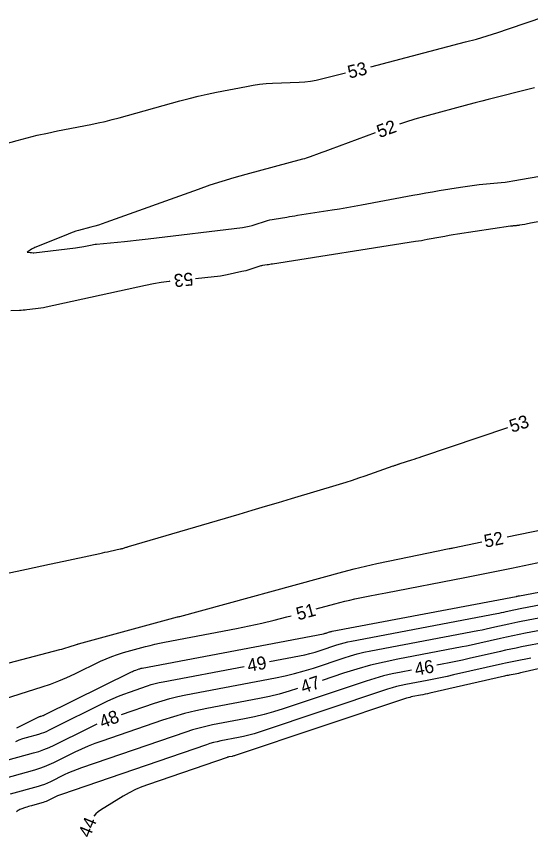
# Model space of a CAD drawing. Extents: x 2384780 to 2405861, y 547869 to 573706.
# Drawn here: x 2390006.1 to 2390085.4, y 552348.1 to 552474.8 of the extents above; entities that cross this region are included whole.
import ezdxf

# ---------------------------------------------------------------- set-up
doc = ezdxf.new("R2010")
doc.units = 0
doc.layers.add('Old_Level_60', color=7, linetype='Continuous')
doc.layers.add('Old_Level_61', color=7, linetype='Continuous')

msp = doc.modelspace()

# ---------------------------------------------------------------- linework, layer by layer
at = {"layer": 'Old_Level_60'}
for points in [[(2390060.75025, 552466.983), (2390075.37925, 552470.815), (2390077.046, 552471.26875), (2390078.70325, 552471.75375), (2390080.351, 552472.27025), (2390081.98925, 552472.81825), (2390087.5915, 552474.752)], [(2389996.453, 552452.94), (2390006.18225, 552455.61525), (2390007.73175, 552456.02575), (2390009.28825, 552456.407), (2390010.8515, 552456.759), (2390012.42175, 552457.082), (2390017.562, 552458.089), (2390018.66125, 552458.31525), (2390019.75525, 552458.56225), (2390020.8445, 552458.83025), (2390021.929, 552459.11875), (2390031.29975, 552461.7095), (2390032.6995, 552462.0825), (2390034.10525, 552462.42925), (2390035.5175, 552462.75), (2390036.93575, 552463.0445), (2390041.579, 552463.9635), (2390042.57625, 552464.14125), (2390043.578, 552464.28025), (2390044.5845, 552464.381), (2390045.5955, 552464.443), (2390049.6985, 552464.6165), (2390050.57475, 552464.6755), (2390051.4445, 552464.7785), (2390052.308, 552464.925), (2390053.16525, 552465.1155), (2390056.8645, 552466.03475)], [(2390086.025, 552463.72925), (2390084.58675, 552463.36875), (2390079.885, 552462.2035), (2390078.87825, 552461.951), (2390077.873, 552461.693), (2390076.869, 552461.429), (2390075.86675, 552461.15975), (2390069.0175, 552459.29775), (2390067.555, 552458.88275), (2390066.1025, 552458.43625), (2390065.1825, 552458.131)], [(2390061.418, 552456.77975), (2390054.48675, 552454.224), (2390054.06225, 552454.0675), (2390053.638, 552453.911), (2390053.2135, 552453.7545), (2390052.78925, 552453.598), (2390051.403, 552453.08675), (2390051.10475, 552452.98075), (2390050.8045, 552452.8815), (2390050.502, 552452.78925), (2390050.19725, 552452.704), (2390041.478, 552450.37075), (2390039.61575, 552449.8515), (2390037.7655, 552449.293), (2390035.92775, 552448.6955), (2390034.102, 552448.05925), (2390019.879, 552442.933), (2390019.30625, 552442.73375), (2390018.7295, 552442.5475), (2390018.14875, 552442.3745), (2390017.564, 552442.21425), (2390015.647, 552441.71225), (2390015.23825, 552441.598), (2390014.834, 552441.471), (2390014.434, 552441.331), (2390014.03825, 552441.178), (2390009.0775, 552439.1685), (2390008.906, 552439.0945), (2390008.738, 552439.01325), (2390008.57375, 552438.925), (2390008.41325, 552438.82925), (2390007.8025, 552438.4475), (2390007.75525, 552438.41125), (2390007.74325, 552438.38425), (2390007.76675, 552438.36625), (2390007.82575, 552438.35725)], [(2390007.82575, 552438.35725), (2390008.18325, 552438.33675), (2390008.24025, 552438.33325), (2390008.29725, 552438.32925), (2390008.354, 552438.32475), (2390008.411, 552438.32), (2390008.65275, 552438.2985), (2390008.6645, 552438.2975), (2390008.6765, 552438.297), (2390008.68825, 552438.297), (2390008.70025, 552438.29725), (2390008.739, 552438.29875), (2390008.74725, 552438.299), (2390008.7555, 552438.2995), (2390008.764, 552438.30025), (2390008.77225, 552438.30125), (2390015.169, 552439.04025), (2390015.49575, 552439.082), (2390015.821, 552439.132), (2390016.145, 552439.19), (2390016.4675, 552439.25625), (2390017.51925, 552439.486), (2390017.74525, 552439.53175), (2390017.97225, 552439.57075), (2390018.20025, 552439.60325), (2390018.42925, 552439.629), (2390022.72825, 552440.04725), (2390023.64925, 552440.13975), (2390024.56975, 552440.2375), (2390025.4895, 552440.3405), (2390026.40875, 552440.449), (2390040.97675, 552442.2115), (2390041.47425, 552442.284), (2390041.9665, 552442.38075), (2390042.4535, 552442.50125), (2390042.935, 552442.646), (2390044.49925, 552443.1575), (2390044.836, 552443.2605), (2390045.17625, 552443.3505), (2390045.5195, 552443.427), (2390045.866, 552443.49025), (2390047.7965, 552443.80425), (2390048.21025, 552443.87125), (2390048.624, 552443.9375), (2390049.038, 552444.00325), (2390049.452, 552444.06825), (2390054.77, 552444.90025), (2390055.90875, 552445.0825), (2390057.04625, 552445.27325), (2390058.18225, 552445.47225), (2390059.317, 552445.6795), (2390067.2235, 552447.1535), (2390068.23875, 552447.34), (2390069.25475, 552447.522), (2390070.27175, 552447.699), (2390071.2895, 552447.871), (2390074.61575, 552448.42525), (2390075.3295, 552448.5375), (2390076.04475, 552448.63725), (2390076.76175, 552448.724), (2390077.48025, 552448.79775), (2390080.29325, 552449.06175), (2390080.89525, 552449.1245), (2390081.49575, 552449.19925), (2390082.09425, 552449.28625), (2390082.69125, 552449.3855), (2390090.682, 552450.796)], [(2390113.026, 552447.73525), (2390085.41125, 552442.83475), (2390085.185, 552442.7945), (2390084.9585, 552442.7545), (2390084.73225, 552442.7145), (2390084.50575, 552442.6745), (2390083.725, 552442.5365), (2390083.587, 552442.51375), (2390083.4485, 552442.4935), (2390083.30975, 552442.47625), (2390083.1705, 552442.46175), (2390082.7155, 552442.419), (2390082.618, 552442.40925), (2390082.52075, 552442.398), (2390082.4235, 552442.3855), (2390082.3265, 552442.3715), (2390074.117, 552441.137), (2390073.47325, 552441.0375), (2390072.83025, 552440.932), (2390072.1885, 552440.821), (2390071.5475, 552440.7045), (2390069.455, 552440.3145), (2390069.00625, 552440.2325), (2390068.557, 552440.15375), (2390068.10725, 552440.0785), (2390067.657, 552440.00625), (2390045.5795, 552436.55275), (2390045.37, 552436.51975), (2390045.16025, 552436.4865), (2390044.95075, 552436.45275), (2390044.74125, 552436.419), (2390044.057, 552436.3075), (2390043.911, 552436.281), (2390043.76625, 552436.24875), (2390043.623, 552436.211), (2390043.48125, 552436.1675), (2390042.0745, 552435.7075), (2390041.772, 552435.61275), (2390041.46725, 552435.526), (2390041.1605, 552435.447), (2390040.85175, 552435.376), (2390038.564, 552434.881), (2390038.07275, 552434.782), (2390037.57925, 552434.6975), (2390037.0835, 552434.6275), (2390036.58525, 552434.57175), (2390033.703, 552434.29125)], [(2390029.72375, 552433.887), (2390029.64225, 552433.87775), (2390028.425, 552433.70475), (2390027.21325, 552433.49575), (2390026.00725, 552433.25125), (2390010.6645, 552429.902), (2390010.258, 552429.81875), (2390009.84975, 552429.7455), (2390009.43975, 552429.6825), (2390009.028, 552429.62975), (2390007.68025, 552429.474), (2390007.39125, 552429.4435), (2390007.10175, 552429.4185), (2390006.812, 552429.39925), (2390006.52175, 552429.3855), (2390005.18, 552429.3355)], [(2390002.024, 552388.313), (2390007.60775, 552389.471), (2390008.804, 552389.7205), (2390009.99975, 552389.9725), (2390011.19475, 552390.2275), (2390012.3895, 552390.485), (2390018.9345, 552391.90375), (2390019.328, 552391.98925), (2390019.72125, 552392.07475), (2390020.1145, 552392.16075), (2390020.50775, 552392.247), (2390022.085, 552392.593), (2390022.2135, 552392.6225), (2390022.3415, 552392.65425), (2390022.469, 552392.68825), (2390022.59575, 552392.72475), (2390023.00875, 552392.84725), (2390023.09725, 552392.8735), (2390023.186, 552392.8995), (2390023.2745, 552392.92575), (2390023.363, 552392.95175), (2390040.45075, 552397.97675), (2390042.46825, 552398.57175), (2390044.48525, 552399.16975), (2390046.501, 552399.771), (2390048.516, 552400.375), (2390055.9445, 552402.60875), (2390056.92925, 552402.91075), (2390057.91025, 552403.22375), (2390058.88775, 552403.5475), (2390059.8615, 552403.88225), (2390064.18125, 552405.394), (2390064.28975, 552405.432), (2390064.3985, 552405.4695), (2390064.50725, 552405.50675), (2390064.61625, 552405.5435), (2390064.97225, 552405.66375), (2390065.0485, 552405.68925), (2390065.125, 552405.71425), (2390065.20175, 552405.73925), (2390065.2785, 552405.7635), (2390067.07725, 552406.3305), (2390067.4625, 552406.453), (2390067.84675, 552406.5775), (2390068.2305, 552406.70425), (2390068.6135, 552406.83325), (2390081.88025, 552411.33725)], [(2390081.803, 552394.48775), (2390098.54775, 552397.934)], [(2389988.47825, 552370.69975), (2390012.75875, 552377.06075), (2390013.07925, 552377.14675), (2390013.39875, 552377.23675), (2390013.71725, 552377.3305), (2390014.03475, 552377.428), (2390015.48125, 552377.88175), (2390015.497, 552377.887), (2390015.51275, 552377.893), (2390015.528, 552377.8995), (2390015.54325, 552377.9065), (2390015.59225, 552377.9305), (2390015.60275, 552377.93525), (2390015.61375, 552377.93975), (2390015.62475, 552377.9435), (2390015.63575, 552377.947), (2390030.90325, 552382.10725), (2390030.939, 552382.1165), (2390030.97475, 552382.12525), (2390031.011, 552382.13325), (2390031.047, 552382.1405), (2390031.16575, 552382.16325), (2390031.191, 552382.16825), (2390031.21625, 552382.17375), (2390031.24125, 552382.18), (2390031.26625, 552382.1865), (2390056.44475, 552389.0425), (2390058.17925, 552389.5005), (2390059.92, 552389.9315), (2390061.6675, 552390.33575), (2390063.42125, 552390.71325), (2390071.16525, 552392.3175), (2390071.39275, 552392.36425), (2390071.6205, 552392.41025), (2390071.8485, 552392.4555), (2390072.0765, 552392.49975), (2390072.82175, 552392.6435), (2390072.9815, 552392.6745), (2390073.141, 552392.706), (2390073.3005, 552392.738), (2390073.46, 552392.7705), (2390077.885, 552393.68125)], [(2390052.30775, 552383.349), (2390055.19325, 552384.13475), (2390055.966, 552384.33875), (2390056.7415, 552384.53075), (2390057.52, 552384.711), (2390058.30125, 552384.879), (2390060.85825, 552385.40875), (2390061.40625, 552385.5215), (2390061.95475, 552385.632), (2390062.50375, 552385.74075), (2390063.053, 552385.84775), (2390075.27075, 552388.20175), (2390077.06925, 552388.55125), (2390078.86675, 552388.9065), (2390080.663, 552389.2675), (2390082.458, 552389.634), (2390088.32025, 552390.8405)], [(2390045.118, 552375.22925), (2390049.741, 552376.1075), (2390050.552, 552376.27575), (2390051.356, 552376.471), (2390052.153, 552376.693), (2390052.943, 552376.94225), (2390055.51225, 552377.8), (2390056.06525, 552377.97425), (2390056.62325, 552378.1295), (2390057.186, 552378.266), (2390057.754, 552378.38325), (2390080.2245, 552382.63475), (2390080.58275, 552382.7045), (2390080.9405, 552382.7775), (2390081.2975, 552382.854), (2390081.65375, 552382.934), (2390082.81625, 552383.2005), (2390083.0655, 552383.2565), (2390083.3155, 552383.31), (2390083.56575, 552383.361), (2390083.81675, 552383.40975), (2390098.63925, 552386.21275)], [(2390022.25675, 552367.03975), (2390027.3615, 552368.788), (2390028.55025, 552369.1715), (2390029.75025, 552369.51225), (2390030.96175, 552369.81), (2390032.1845, 552370.065), (2390046.02475, 552372.69425), (2390047.5135, 552373.00325), (2390048.98975, 552373.3615), (2390050.45275, 552373.76925), (2390051.903, 552374.2265), (2390056.61925, 552375.801), (2390057.6345, 552376.121), (2390058.65875, 552376.40625), (2390059.692, 552376.6565), (2390060.73425, 552376.872), (2390077.24775, 552379.9965), (2390077.915, 552380.126), (2390078.581, 552380.262), (2390079.2455, 552380.4045), (2390079.90875, 552380.55325), (2390082.07325, 552381.04975), (2390082.5375, 552381.15375), (2390083.00275, 552381.2535), (2390083.46875, 552381.34875), (2390083.936, 552381.43925), (2390094.02025, 552383.34625)], [(2390003.0285, 552369.12), (2390010.0565, 552371.32525), (2390011.33925, 552371.7545), (2390012.60325, 552372.23075), (2390013.84825, 552372.7545), (2390015.07475, 552373.32525), (2390019.04975, 552375.26725), (2390019.90925, 552375.6625), (2390020.78475, 552376.01625), (2390021.67575, 552376.328), (2390022.58275, 552376.598), (2390025.9705, 552377.52125), (2390026.698, 552377.712), (2390027.429, 552377.8885), (2390028.163, 552378.051), (2390028.9005, 552378.19925), (2390040.05, 552380.32875), (2390041.9975, 552380.72025), (2390043.9365, 552381.149), (2390045.86675, 552381.615), (2390047.78825, 552382.1185), (2390048.44825, 552382.29825)], [(2390090.63175, 552380.7125), (2390084.6415, 552379.57975), (2390083.66525, 552379.39025), (2390082.69125, 552379.19125), (2390081.719, 552378.983), (2390080.74875, 552378.7655), (2390077.5825, 552378.03925), (2390076.90325, 552377.88675), (2390076.22275, 552377.741), (2390075.54075, 552377.60175), (2390074.8575, 552377.469), (2390064.92475, 552375.58975), (2390062.8055, 552375.1515), (2390060.70475, 552374.64275), (2390058.62225, 552374.063), (2390056.55825, 552373.41225), (2390053.26125, 552372.3115)], [(2390109.3895, 552379.307), (2390084.11125, 552373.52175), (2390083.83975, 552373.461), (2390083.56775, 552373.40275), (2390083.29525, 552373.34725), (2390083.022, 552373.29425), (2390082.12925, 552373.1255), (2390081.938, 552373.08825), (2390081.74725, 552373.04925), (2390081.55675, 552373.0085), (2390081.36675, 552372.966), (2390069.86525, 552370.3275), (2390069.5075, 552370.2475), (2390069.14925, 552370.1705), (2390068.79025, 552370.09725), (2390068.43025, 552370.0275), (2390067.25375, 552369.80475), (2390067.00275, 552369.753), (2390066.754, 552369.69275), (2390066.50725, 552369.624), (2390066.26275, 552369.547), (2390039.84475, 552360.727), (2390039.72, 552360.68775), (2390039.59425, 552360.65275), (2390039.4675, 552360.622), (2390039.3395, 552360.5955), (2390038.91975, 552360.51575), (2390038.83025, 552360.497), (2390038.7415, 552360.47525), (2390038.6535, 552360.45025), (2390038.5665, 552360.42225), (2390026.45175, 552356.2735), (2390025.43825, 552355.8955), (2390024.44975, 552355.464), (2390023.4865, 552354.979), (2390022.548, 552354.44075), (2390019.058, 552352.31125), (2390018.66475, 552352.0365), (2390018.316, 552351.71925), (2390018.0375, 552351.3905)], [(2390087.84575, 552378.1925), (2390084.01525, 552377.46825), (2390083.19525, 552377.309), (2390082.377, 552377.142), (2390081.56025, 552376.967), (2390080.74525, 552376.78425), (2390075.9305, 552375.67975), (2390074.89775, 552375.448), (2390073.863, 552375.2265), (2390072.826, 552375.01475), (2390071.787, 552374.813), (2390070.955, 552374.6555)], [(2390005.95375, 552362.9085), (2390006.5035, 552363.13475), (2390007.0635, 552363.33425), (2390007.63375, 552363.5075), (2390009.51275, 552364.03025), (2390009.912, 552364.1515), (2390010.30425, 552364.291), (2390010.68925, 552364.44875), (2390011.0675, 552364.625), (2390020.186, 552369.13575), (2390020.998, 552369.5215), (2390021.8215, 552369.88), (2390022.656, 552370.212), (2390023.50175, 552370.51675), (2390026.28275, 552371.46925), (2390026.8815, 552371.6625), (2390027.486, 552371.834), (2390028.09625, 552371.984), (2390028.712, 552372.1125), (2390041.18825, 552374.48275)], [(2390067.02475, 552373.91175), (2390065.42275, 552373.60875), (2390064.06475, 552373.328), (2390062.71875, 552373.002), (2390061.3845, 552372.6305), (2390060.062, 552372.2135), (2390047.2235, 552367.9275), (2390045.75825, 552367.4655), (2390044.28, 552367.05325), (2390042.7885, 552366.69125), (2390041.28425, 552366.37925), (2390036.34875, 552365.44175), (2390035.29625, 552365.22225), (2390034.25325, 552364.966), (2390033.22, 552364.6725), (2390032.19675, 552364.34225), (2390016.1215, 552358.83725), (2390015.4385, 552358.591), (2390014.76475, 552358.32325), (2390014.1, 552358.0335), (2390013.44425, 552357.72225), (2390011.31675, 552356.66975), (2390010.85675, 552356.4555), (2390010.388, 552356.26325), (2390009.91075, 552356.0935), (2390009.425, 552355.94625), (2390005.088, 552354.73975)], [(2390049.46625, 552371.04775), (2390048.13875, 552370.629), (2390046.63425, 552370.20975), (2390045.11625, 552369.84125), (2390043.58525, 552369.52375), (2390035.462, 552367.9805), (2390033.72925, 552367.61925), (2390032.01275, 552367.19725), (2390030.3125, 552366.7145), (2390028.628, 552366.171), (2390019.22575, 552362.95125), (2390018.1685, 552362.57), (2390017.1255, 552362.155), (2390016.09625, 552361.70675), (2390015.081, 552361.22475), (2390011.7875, 552359.5955), (2390011.07525, 552359.26375), (2390010.34975, 552358.96625), (2390009.611, 552358.7035), (2390008.859, 552358.47525), (2390001.80825, 552356.51425)], [(2389984.44275, 552345.56175), (2389994.68475, 552354.667), (2389995.56475, 552355.399), (2389996.48725, 552356.068), (2389997.45225, 552356.674), (2389998.45975, 552357.217), (2390001.82025, 552358.8885), (2390002.54725, 552359.22875), (2390003.288, 552359.5335), (2390004.04225, 552359.8025), (2390004.81025, 552360.03575), (2390008.686, 552361.11375), (2390009.50925, 552361.36375), (2390010.31825, 552361.65125), (2390011.1125, 552361.977), (2390011.8925, 552362.34025), (2390017.1815, 552364.95675), (2390018.32275, 552365.4985), (2390018.53075, 552365.58925)]]:
    msp.add_lwpolyline(points, dxfattribs=at)
at = {"layer": 'Old_Level_61'}
for points in [[(2390006.1255, 552364.98975), (2390009.54325, 552366.6895), (2390009.62525, 552366.728), (2390009.709, 552366.7625), (2390009.79425, 552366.79275), (2390009.88075, 552366.81925), (2390010.16675, 552366.89875), (2390010.2275, 552366.917), (2390010.287, 552366.93825), (2390010.34575, 552366.96225), (2390010.40325, 552366.989), (2390023.84525, 552373.639), (2390023.99875, 552373.71175), (2390024.154, 552373.7795), (2390024.31175, 552373.842), (2390024.47125, 552373.89975), (2390024.9965, 552374.0795), (2390025.1095, 552374.116), (2390025.2235, 552374.14825), (2390025.33875, 552374.17675), (2390025.455, 552374.201), (2390053.45725, 552379.52075), (2390053.5905, 552379.5485), (2390053.7225, 552379.5805), (2390053.8535, 552379.617), (2390053.98325, 552379.658), (2390054.40525, 552379.79875), (2390054.496, 552379.8275), (2390054.58775, 552379.853), (2390054.68025, 552379.87525), (2390054.7735, 552379.8945), (2390083.201, 552385.27325), (2390083.2505, 552385.28275), (2390083.3, 552385.293), (2390083.34925, 552385.3035), (2390083.3985, 552385.3145), (2390083.55925, 552385.3515), (2390083.59375, 552385.35925), (2390083.62825, 552385.3665), (2390083.66275, 552385.3735), (2390083.6975, 552385.38025), (2390102.61475, 552388.95775)], [(2390085.434, 552375.7435), (2390083.07225, 552375.29675), (2390082.56675, 552375.19875), (2390082.062, 552375.09575), (2390081.5585, 552374.98775), (2390081.056, 552374.875), (2390073.5285, 552373.14825), (2390072.51775, 552372.9215), (2390071.50475, 552372.7045), (2390070.49, 552372.49725), (2390069.473, 552372.3), (2390066.1475, 552371.67075), (2390065.438, 552371.524), (2390064.73475, 552371.3535), (2390064.0375, 552371.1595), (2390063.3465, 552370.94175), (2390043.534, 552364.32725), (2390042.73925, 552364.0765), (2390041.937, 552363.853), (2390041.128, 552363.65675), (2390040.312, 552363.4875), (2390037.63425, 552362.97875), (2390037.06325, 552362.85975), (2390036.49725, 552362.7205), (2390035.93675, 552362.5615), (2390035.38175, 552362.38225), (2390013.017, 552354.7235), (2390012.7085, 552354.61225), (2390012.404, 552354.49125), (2390012.10375, 552354.36025), (2390011.80725, 552354.2195), (2390010.846, 552353.744), (2390010.638, 552353.64725), (2390010.42625, 552353.5605), (2390010.21075, 552353.48375), (2390009.99125, 552353.417), (2390008.36775, 552352.9655), (2390008.143, 552352.90125), (2390007.9195, 552352.834), (2390007.69675, 552352.7635), (2390007.47525, 552352.68975), (2390006.75275, 552352.444), (2390006.60225, 552352.384), (2390006.46, 552352.30975), (2390006.3265, 552352.221), (2390006.2015, 552352.118), (2390006.10225, 552352.0275)]]:
    msp.add_lwpolyline(points, dxfattribs=at)

# ---------------------------------------------------------------- texts
at = {"layer": 'Old_Level_60'}
for s, rotation, p in [('53', 13.7143528, (2390057.44575, 552465.14825)), ('52', 19.7428861, (2390062.0985, 552455.97925)), ('53', 185.8006417, (2390033.2485, 552435.2585)), ('53', 18.752075, (2390082.5375, 552410.50425)), ('52', 11.6299611, (2390078.44925, 552392.7765)), ('51', 15.2321056, (2390049.547, 552381.56075)), ('49', 10.7569167, (2390041.8855, 552373.59725)), ('46', 10.7139889, (2390067.7215, 552373.026)), ('47', 18.4205361, (2390050.32075, 552370.27675)), ('48', 21.2731611, (2390019.338, 552364.88175)), ('44', 67.6582083, (2390017.38675, 552347.91825))]:
    msp.add_text(s, height=2, rotation=rotation, dxfattribs=at).set_placement(p)

doc.saveas('drawing.dxf')
